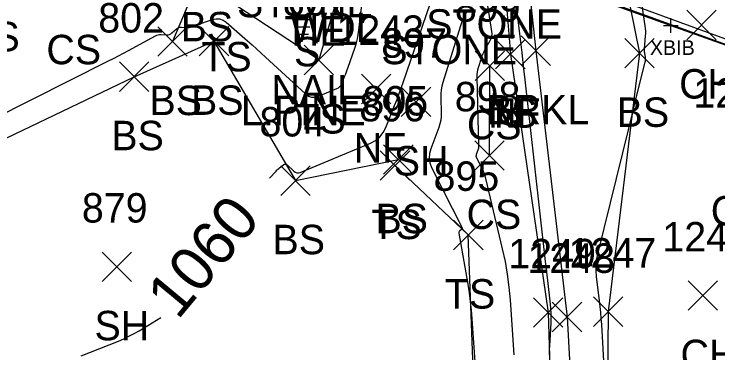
# Model space of a CAD drawing. Extents: x 1592612 to 1596497, y 111838 to 113741.
# Drawn here: x 1592834.42 to 1592882.21, y 113419.92 to 113442.94 of the extents above; entities that cross this region are included whole.
import ezdxf

# ---------------------------------------------------------------- set-up
doc = ezdxf.new("R2010")
doc.units = 0
for name, color, linetype in [('B_A', 7, 'Continuous'), ('B_TIC', 7, 'Continuous'), ('BB', 7, 'Continuous'), ('BELB', 7, 'Continuous'), ('BR', 7, 'Continuous'), ('C_A', 7, 'Continuous'), ('C_C', 7, 'Continuous'), ('L_A', 7, 'Continuous'), ('L_C', 7, 'Continuous'), ('L_I', 7, 'Continuous'), ('L_TIC', 7, 'Continuous'), ('LAWE', 7, 'Continuous'), ('LELB', 7, 'Continuous'), ('LSOGCMA', 7, 'Continuous'), ('LSOGCMA_T', 7, 'Continuous'), ('LSOGCMI', 7, 'Continuous'), ('LTC', 7, 'Continuous')]:
    doc.layers.add(name, color=color, linetype=linetype)

msp = doc.modelspace()

# ---------------------------------------------------------------- linework, layer by layer
at = {"layer": 'B_TIC'}
msp.add_line((1592879.026, 113442.165), (1592879.101, 113442.165), dxfattribs=at)
for points in [[(1592879.022, 113441.665), (1592879.022, 113442.665)], [(1592878.522, 113442.165), (1592879.522, 113442.165)]]:
    msp.add_lwpolyline(points, dxfattribs=at)
at = {"layer": 'BB'}
msp.add_lwpolyline([(1592851.635, 113452.04), (1592879.022, 113442.165), (1592905.868, 113432.599)], dxfattribs=at)
at = {"layer": 'BELB'}
msp.add_lwpolyline([(1592905.752, 113432.884), (1592904.3, 113433.154), (1592890.285, 113438.142), (1592870.936, 113445.184), (1592851.173, 113452.262)], dxfattribs=at)
at = {"layer": 'BR'}
msp.add_lwpolyline([(1592908.092, 113431.674), (1592904.666, 113433.279), (1592893.882, 113437.15), (1592872.402, 113445.033), (1592848.761, 113453.419)], dxfattribs=at)
at = {"layer": 'L_TIC'}
for points in [[(1592880.09, 113441.203), (1592882.09, 113443.203)], [(1592882.09, 113441.203), (1592880.09, 113443.203)], [(1592844.17, 113440.076), (1592846.17, 113442.076)], [(1592846.17, 113440.076), (1592844.17, 113442.076)], [(1592846.993, 113440.095), (1592848.993, 113442.095)], [(1592848.993, 113440.095), (1592846.993, 113442.095)], [(1592867.12, 113439.226), (1592869.12, 113441.226)], [(1592869.12, 113439.226), (1592867.12, 113441.226)], [(1592867.12, 113439.226), (1592869.12, 113441.226)], [(1592869.12, 113439.226), (1592867.12, 113441.226)], [(1592868.843, 113439.453), (1592870.843, 113441.453)], [(1592870.843, 113439.453), (1592868.843, 113441.453)], [(1592875.893, 113439.279), (1592877.893, 113441.279)], [(1592877.893, 113439.279), (1592875.893, 113441.279)], [(1592854.111, 113438.824), (1592856.111, 113440.824)], [(1592856.111, 113438.824), (1592854.111, 113440.824)], [(1592865.725, 113438.429), (1592867.725, 113440.429)], [(1592867.725, 113438.429), (1592865.725, 113440.429)], [(1592841.578, 113437.689), (1592843.578, 113439.689)], [(1592843.578, 113437.689), (1592841.578, 113439.689)], [(1592858, 113436.852), (1592860, 113438.852)], [(1592860, 113436.852), (1592858, 113438.852)], [(1592860.713, 113435.975), (1592862.713, 113437.975)], [(1592862.713, 113435.975), (1592860.713, 113437.975)], [(1592859.515, 113432.053), (1592861.515, 113434.053)], [(1592861.515, 113432.053), (1592859.515, 113434.053)], [(1592865.703, 113432.335), (1592867.703, 113434.335)], [(1592867.703, 113432.335), (1592865.703, 113434.335)], [(1592859.283, 113431.65), (1592861.283, 113433.65)], [(1592861.283, 113431.65), (1592859.283, 113433.65)], [(1592852.522, 113430.625), (1592854.522, 113432.625)], [(1592854.522, 113430.625), (1592852.522, 113432.625)], [(1592864.264, 113426.931), (1592866.264, 113428.931)], [(1592866.264, 113426.931), (1592864.264, 113428.931)], [(1592840.392, 113424.775), (1592842.392, 113426.775)], [(1592842.392, 113424.775), (1592840.392, 113426.775)], [(1592880.186, 113422.815), (1592882.186, 113424.815)], [(1592882.186, 113422.815), (1592880.186, 113424.815)], [(1592869.678, 113421.668), (1592871.678, 113423.668)], [(1592871.678, 113421.668), (1592869.678, 113423.668)], [(1592873.766, 113421.722), (1592875.766, 113423.722)], [(1592875.766, 113421.722), (1592873.766, 113423.722)], [(1592870.967, 113421.356), (1592872.967, 113423.356)], [(1592872.967, 113421.356), (1592870.967, 113423.356)]]:
    msp.add_lwpolyline(points, dxfattribs=at)
at = {"layer": 'LAWE'}
msp.add_lwpolyline([(1592867.923, 113458.263), (1592869.843, 113440.453), (1592871.967, 113422.356), (1592872.93, 113405.001), (1592883.346, 113373.9), (1592893.179, 113344.656), (1592901.657, 113316.308), (1592912.684, 113311.087), (1592910.248, 113308.35), (1592916.07, 113291.076)], dxfattribs=at)
at = {"layer": 'LELB'}
for points in [[(1592866.59, 113458.717), (1592868.12, 113440.226), (1592870.678, 113422.668), (1592871.235, 113404.668), (1592883.079, 113373.124), (1592885.764, 113364.063), (1592892.434, 113344.134), (1592901.184, 113316.355)], [(1592873.192, 113458.509), (1592876.893, 113440.279), (1592874.766, 113422.722), (1592874.598, 113405.543), (1592883.851, 113374.09), (1592893.431, 113344.94), (1592902.258, 113316.43), (1592913.374, 113311.383), (1592911.324, 113309.219), (1592917.546, 113291.093), (1592922.314, 113282.948), (1592911.412, 113283.497), (1592902.691, 113283.749), (1592891.129, 113289.026)], [(1592851.364, 113451.226), (1592847.289, 113446.089), (1592845.17, 113441.076)], [(1592857.94, 113449.406), (1592855.111, 113439.824), (1592848.728, 113444.05)], [(1592823.87, 113376.529), (1592829.701, 113394.688), (1592831.503, 113407.397), (1592828.202, 113424.312), (1592827.942, 113431.685), (1592842.578, 113438.689), (1592847.993, 113441.095), (1592853.522, 113431.624), (1592860.515, 113433.053)], [(1592866.703, 113433.335), (1592866.725, 113439.429)], [(1592879.999, 113371.476), (1592873.828, 113373.577), (1592861.065, 113382.477), (1592862.671, 113391.111), (1592862.826, 113406.961), (1592865.842, 113412.221), (1592865.264, 113427.931), (1592860.283, 113432.65)]]:
    msp.add_lwpolyline(points, dxfattribs=at)
at = {"layer": 'LSOGCMA'}
for points in [[(1592851.76, 113431.794), (1592852.212, 113432.279), (1592852.269, 113432.337), (1592852.327, 113432.394), (1592852.388, 113432.448), (1592852.451, 113432.5), (1592852.705, 113432.704), (1592852.768, 113432.741), (1592852.83, 113432.752), (1592852.892, 113432.737), (1592852.952, 113432.695), (1592853.416, 113432.265), (1592853.517, 113432.192), (1592853.623, 113432.155), (1592853.736, 113432.153), (1592853.856, 113432.187), (1592858.628, 113434.179), (1592858.971, 113434.361), (1592859.258, 113434.598), (1592859.489, 113434.889), (1592859.665, 113435.235), (1592860.257, 113436.729), (1592860.403, 113437.103), (1592860.545, 113437.479), (1592860.682, 113437.856), (1592860.816, 113438.235), (1592862.705, 113443.697)], [(1592838.985, 113419.721), (1592841.501, 113420.724), (1592841.865, 113420.878), (1592842.222, 113421.046), (1592842.572, 113421.229), (1592842.915, 113421.426), (1592844.39, 113422.315)]]:
    msp.add_lwpolyline(points, dxfattribs=at)
at = {"layer": 'LSOGCMI'}
for points in [[(1592874.589, 113417.293), (1592874.32, 113421.839), (1592874.292, 113422.248), (1592874.259, 113422.656), (1592874.219, 113423.064), (1592874.173, 113423.471), (1592873.977, 113425.099), (1592873.947, 113425.505), (1592873.953, 113425.909), (1592873.996, 113426.31), (1592874.075, 113426.709), (1592876.158, 113435.17), (1592876.273, 113435.637), (1592876.388, 113436.104), (1592876.503, 113436.57), (1592876.619, 113437.037), (1592877.278, 113439.689), (1592877.292, 113439.763), (1592877.299, 113439.836), (1592877.299, 113439.91), (1592877.29, 113439.984), (1592877.242, 113440.28), (1592877.233, 113440.354), (1592877.227, 113440.429), (1592877.227, 113440.503), (1592877.23, 113440.578), (1592877.299, 113441.455), (1592877.307, 113441.625), (1592877.306, 113441.796), (1592877.295, 113441.966), (1592877.274, 113442.136), (1592875.051, 113456.937)], [(1592830.355, 113434.496), (1592840.833, 113439.755), (1592841.173, 113439.928), (1592841.513, 113440.103), (1592841.85, 113440.281), (1592842.187, 113440.462), (1592844.027, 113441.461), (1592844.115, 113441.502), (1592844.207, 113441.53), (1592844.301, 113441.545), (1592844.399, 113441.548), (1592844.794, 113441.534), (1592844.89, 113441.539), (1592844.979, 113441.561), (1592845.063, 113441.601), (1592845.139, 113441.658), (1592845.449, 113441.935), (1592845.519, 113441.987), (1592845.595, 113442.023), (1592845.676, 113442.043), (1592845.764, 113442.047), (1592846.124, 113442.032), (1592846.214, 113442.033), (1592846.302, 113442.041), (1592846.389, 113442.059), (1592846.475, 113442.084), (1592847.88, 113442.573), (1592848.136, 113442.63), (1592848.379, 113442.618), (1592848.608, 113442.538), (1592848.824, 113442.389), (1592850.272, 113441.122), (1592850.582, 113440.848), (1592850.89, 113440.573), (1592851.196, 113440.295), (1592851.5, 113440.015), (1592854.197, 113437.517), (1592854.401, 113437.37), (1592854.618, 113437.294), (1592854.848, 113437.29), (1592855.09, 113437.358), (1592856.325, 113437.874), (1592856.444, 113437.937), (1592856.543, 113438.019), (1592856.623, 113438.119), (1592856.684, 113438.239), (1592856.888, 113438.755), (1592856.939, 113438.884), (1592856.988, 113439.014), (1592857.035, 113439.144), (1592857.081, 113439.275), (1592857.574, 113440.701), (1592857.664, 113440.984), (1592857.737, 113441.27), (1592857.795, 113441.561), (1592857.837, 113441.855), (1592858.391, 113446.704)], [(1592868.376, 113419.796), (1592868.119, 113423.524), (1592868.04, 113424.396), (1592867.926, 113425.263), (1592867.777, 113426.124), (1592867.592, 113426.98), (1592866.451, 113431.775), (1592866.408, 113431.936), (1592866.356, 113432.093), (1592866.294, 113432.247), (1592866.224, 113432.398), (1592865.842, 113433.158), (1592865.816, 113433.226), (1592865.805, 113433.295), (1592865.809, 113433.364), (1592865.828, 113433.434), (1592865.934, 113433.716), (1592865.957, 113433.788), (1592865.973, 113433.86), (1592865.982, 113433.933), (1592865.983, 113434.008), (1592865.864, 113438.674), (1592865.867, 113438.838), (1592865.882, 113439), (1592865.912, 113439.16), (1592865.954, 113439.318), (1592866.151, 113439.948), (1592866.205, 113440.104), (1592866.266, 113440.256), (1592866.335, 113440.405), (1592866.412, 113440.551), (1592866.747, 113441.143), (1592866.816, 113441.292), (1592866.858, 113441.446), (1592866.873, 113441.604), (1592866.86, 113441.768), (1592866.244, 113445.696)], [(1592868.25, 113445.857), (1592868.675, 113442.17), (1592868.781, 113441.248), (1592868.886, 113440.327), (1592868.99, 113439.405), (1592869.094, 113438.483), (1592870.457, 113426.328), (1592870.499, 113425.957), (1592870.542, 113425.585), (1592870.585, 113425.214), (1592870.629, 113424.843), (1592870.821, 113423.238), (1592870.852, 113422.927), (1592870.869, 113422.614), (1592870.872, 113422.302), (1592870.861, 113421.989), (1592870.792, 113420.735), (1592870.775, 113420.422), (1592870.761, 113420.108), (1592870.748, 113419.795)], [(1592865.119, 113443.029), (1592864.972, 113442.769), (1592864.937, 113442.703), (1592864.905, 113442.635), (1592864.877, 113442.566), (1592864.853, 113442.496), (1592863.536, 113438.287), (1592863.469, 113438.038), (1592863.423, 113437.786), (1592863.399, 113437.531), (1592863.395, 113437.274), (1592863.421, 113436.238), (1592863.416, 113435.981), (1592863.386, 113435.728), (1592863.331, 113435.479), (1592863.252, 113435.234), (1592862.707, 113433.786), (1592862.62, 113433.466), (1592862.602, 113433.149), (1592862.653, 113432.836), (1592862.773, 113432.527), (1592864.859, 113428.372), (1592864.86, 113428.368), (1592864.86, 113428.364), (1592864.859, 113428.361), (1592864.855, 113428.358), (1592864.839, 113428.347), (1592864.831, 113428.341), (1592864.824, 113428.335), (1592864.66, 113428.19), (1592864.636, 113428.163), (1592864.62, 113428.133), (1592864.614, 113428.1), (1592864.616, 113428.064), (1592865.223, 113424.599), (1592865.319, 113424.009), (1592865.399, 113423.416), (1592865.463, 113422.821), (1592865.512, 113422.225), (1592866.139, 113413.172)]]:
    msp.add_lwpolyline(points, dxfattribs=at)
at = {"layer": 'LTC'}
for p, q in [((1592854.588, 113442.555), (1592853.599, 113442.555)), ((1592854.504, 113442.055), (1592853.672, 113442.055)), ((1592854.42, 113441.555), (1592853.745, 113441.555))]:
    msp.add_line(p, q, dxfattribs=at)

# ---------------------------------------------------------------- texts
at = {"layer": 'B_A'}
msp.add_text('XBIB', height=1, dxfattribs=at).set_placement((1592877.593, 113440.165))
at = {"layer": 'C_A'}
msp.add_text('TIE', height=2, dxfattribs=at).set_placement((1592852.786, 113440.804))
at = {"layer": 'C_C'}
msp.add_text('NAIL', height=2, dxfattribs=at).set_placement((1592851.889, 113436.804))
at = {"layer": 'L_A'}
for s, p in [('STONE', (1592849.559, 113442.728)), ('BS', (1592845.729, 113441.089)), ('WDL', (1592853.16, 113441.044)), ('STONE', (1592862.407, 113441.27)), ('CS', (1592831.09, 113440.415)), ('CS', (1592836.612, 113439.533)), ('S', (1592853.43, 113439.392)), ('STONE', (1592859.36, 113439.537)), ('TS', (1592847.137, 113439.05)), ('CH', (1592879.578, 113437.203)), ('BS', (1592843.611, 113436.076)), ('BS', (1592846.434, 113436.095)), ('BRKL', (1592866.488, 113435.453)), ('BS', (1592875.334, 113435.279)), ('TS', (1592853.52, 113434.824)), ('TS', (1592866.529, 113435.226)), ('NF', (1592866.6, 113435.226)), ('CS', (1592865.166, 113434.429)), ('BS', (1592841.019, 113433.689)), ('NF', (1592857.481, 113432.852)), ('SH', (1592860.201, 113431.975)), ('CH', (1592881.726, 113428.585)), ('CS', (1592865.144, 113428.335)), ('TS', (1592858.692, 113427.65)), ('BS', (1592858.956, 113428.053)), ('BS', (1592851.963, 113426.625)), ('TS', (1592863.673, 113422.931)), ('SH', (1592839.88, 113420.775)), ('CH', (1592879.674, 113418.815))]:
    msp.add_text(s, height=2, dxfattribs=at).set_placement(p)
at = {"layer": 'L_C'}
msp.add_text('L.PINE', height=2, dxfattribs=at).set_placement((1592849.823, 113435.392))
at = {"layer": 'L_I'}
for s, p in [('807', (1592852.67, 113442.824)), ('899', (1592864.355, 113442.429)), ('802', (1592840.137, 113441.689)), ('1243', (1592856.307, 113440.852)), ('897', (1592859.351, 113439.975)), ('898', (1592864.341, 113436.335)), ('1244', (1592880.545, 113436.585)), ('805', (1592858.074, 113436.053)), ('896', (1592857.865, 113435.65)), ('804', (1592851.081, 113434.625)), ('895', (1592862.902, 113430.931)), ('879', (1592839.022, 113428.775)), ('1246', (1592878.438, 113426.815)), ('1247', (1592872.073, 113425.722)), ('1249', (1592867.977, 113425.668)), ('1248', (1592869.274, 113425.356))]:
    msp.add_text(s, height=2, dxfattribs=at).set_placement(p)
at = {"layer": 'LSOGCMA_T'}
msp.add_text('1060', height=3, rotation=50.229, dxfattribs=at).set_placement((1592845.53, 113422.104))

doc.saveas('drawing.dxf')
